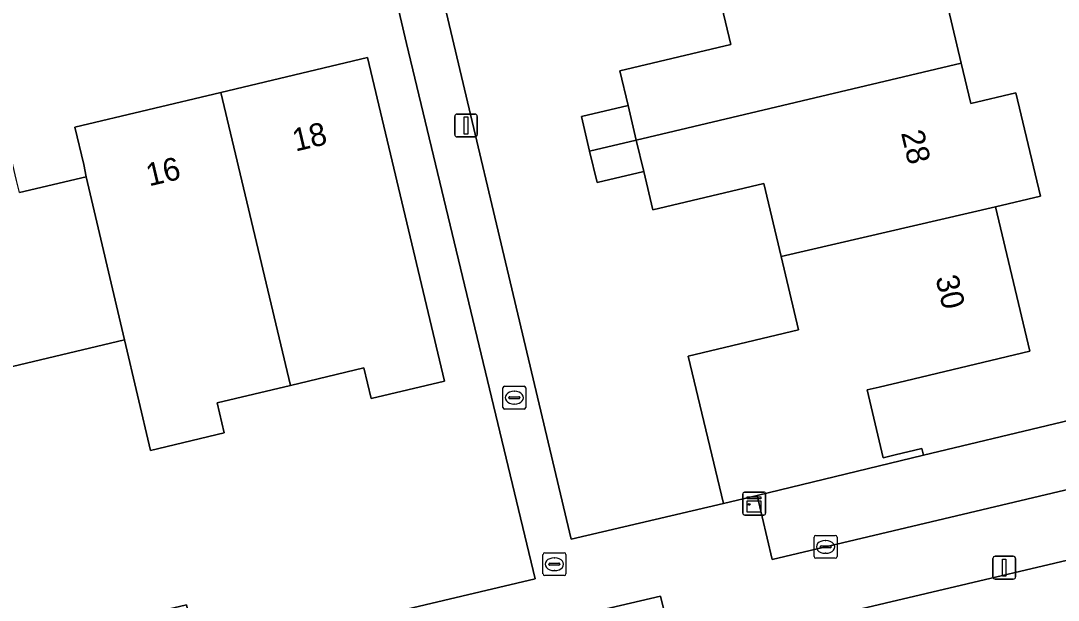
# Model space of a CAD drawing. Extents: x 157648 to 158502, y 379212 to 380938.
# Drawn here: x 158306.48 to 158351.9, y 380807.19 to 380832.57 of the extents above; entities that cross this region are included whole.
import ezdxf

# ---------------------------------------------------------------- set-up
doc = ezdxf.new("R2010")
doc.units = 0
for name, color, linetype in [('IMGEO_Erf', 7, 'Continuous'), ('IMGEO_Groenvoorziening', 7, 'Continuous'), ('IMGEO_Hek', 7, 'Continuous'), ('IMGEO_Kast', 7, 'Continuous'), ('IMGEO_Kolk', 7, 'Continuous'), ('IMGEO_Lichtmast', 7, 'Continuous'), ('IMGEO_Pand', 7, 'Continuous'), ('IMGEO_Pand_nummerreeks', 7, 'Continuous'), ('IMGEO_Rioolput', 7, 'Continuous'), ('IMGEO_Voetpad_open', 7, 'Continuous')]:
    doc.layers.add(name, color=color, linetype=linetype)

msp = doc.modelspace()

# ---------------------------------------------------------------- linework, layer by layer
at = {"layer": 'IMGEO_Erf'}
for points in [[(158346.135, 380837.142), (158347.662, 380830.717), (158348.081, 380828.951), (158350.047, 380829.418), (158351.124, 380824.885), (158349.158, 380824.417), (158350.661, 380818.095), (158345.233, 380816.805), (158344.065, 380816.528), (158343.54, 380816.403), (158344.245, 380813.436), (158344.77, 380813.561), (158345.938, 380813.838), (158346.006, 380813.552), (158363.215, 380817.667), (158352.177, 380864.073)], [(158322.972, 380841.959), (158330.575, 380809.862), (158337.257, 380811.425), (158335.708, 380817.882), (158340.536, 380819.029), (158339.773, 380822.239), (158339.011, 380825.447), (158334.155, 380824.294), (158333.757, 380825.967), (158331.714, 380825.482), (158331.389, 380826.851), (158331.028, 380828.372), (158333.071, 380828.856), (158332.71, 380830.377), (158337.566, 380831.531), (158336.781, 380834.836)], [(158278.284, 380798.647), (158313.745, 380806.99), (158314.304, 380804.661), (158329, 380808.131), (158323.379, 380831.566), (158321.058, 380841.488)], [(158306.43, 380825.041), (158309.351, 380825.735), (158309.248, 380826.274), (158308.859, 380827.913), (158315.246, 380829.43), (158321.667, 380830.956), (158325.033, 380816.793), (158321.823, 380816.03), (158321.506, 380817.366), (158318.291, 380816.602), (158315.077, 380815.839), (158315.39, 380814.522), (158312.17, 380813.757), (158311.02, 380818.596), (158304.887, 380817.139)], [(158364.564, 380811.841), (158335.11, 380804.894), (158334.498, 380807.379), (158318.481, 380803.643), (158321.807, 380789.612), (158323.266, 380789.958), (158322.059, 380795.081), (158328.42, 380796.648), (158334.809, 380798.161), (158337.107, 380788.456), (158338.879, 380788.876), (158340.617, 380789.288), (158338.891, 380796.576), (158345.168, 380798.063), (158351.466, 380799.554), (158357.767, 380801.046)]]:
    msp.add_lwpolyline(points, dxfattribs=at)
at = {"layer": 'IMGEO_Groenvoorziening'}
msp.add_lwpolyline([(158363.902, 380814.78), (158363.215, 380817.667), (158346.006, 380813.552), (158338.72, 380811.781), (158339.383, 380808.977)], close=True, dxfattribs=at)
at = {"layer": 'IMGEO_Hek'}
for points in [[(158337.257, 380811.425), (158330.575, 380809.862), (158322.972, 380841.959)], [(158323.379, 380831.566), (158329, 380808.131), (158314.304, 380804.661), (158313.745, 380806.99), (158278.284, 380798.647)]]:
    msp.add_lwpolyline(points, dxfattribs=at)
at = {"layer": 'IMGEO_Kast'}
for p, q in [((158338.169, 380811.926), (158339.01, 380811.926)), ((158339.01, 380811.926), (158338.169, 380811.926)), ((158338.094, 380811.001), (158338.094, 380811.842)), ((158338.094, 380811.842), (158338.094, 380811.001)), ((158339.094, 380811.851), (158339.094, 380811.01)), ((158339.094, 380811.01), (158339.094, 380811.851)), ((158339.019, 380810.926), (158338.178, 380810.926)), ((158338.178, 380810.926), (158339.019, 380810.926))]:
    msp.add_line(p, q, dxfattribs=at)
for points in [[(158338.289, 380811.716), (158338.889, 380811.716), (158338.889, 380811.631), (158338.289, 380811.631), (158338.289, 380811.716)], [(158338.289, 380811.541), (158338.889, 380811.541), (158338.889, 380811.052), (158338.289, 380811.052), (158338.289, 380811.541)]]:
    msp.add_lwpolyline(points, dxfattribs=at)
msp.add_circle((158338.373, 380811.39), 0.0377, dxfattribs=at)
for centre, start, end in [((158338.172, 380811.848), 92.4484, 184.2845), ((158338.172, 380811.848), 92.4484, 184.2845), ((158339.016, 380811.848), 2.4484, 94.2845), ((158339.016, 380811.848), 2.4484, 94.2845), ((158338.172, 380811.004), 182.4484, 274.2845), ((158338.172, 380811.004), 182.4484, 274.2845), ((158339.016, 380811.004), 272.4484, 4.2845), ((158339.016, 380811.004), 272.4484, 4.2845)]:
    msp.add_arc(centre, 0.0779, start, end, dxfattribs=at)
at = {"layer": 'IMGEO_Kolk'}
for p, q in [((158327.592, 380815.637), (158327.592, 380816.489)), ((158327.667, 380816.563), (158328.519, 380816.563)), ((158328.593, 380816.489), (158328.593, 380815.637)), ((158327.851, 380816.057), (158327.851, 380816.069)), ((158328.289, 380816.02), (158327.891, 380816.02)), ((158327.894, 380816.106), (158328.292, 380816.106)), ((158328.08, 380816.343), (158328.105, 380816.343)), ((158328.335, 380816.069), (158328.335, 380816.057)), ((158328.519, 380815.563), (158327.667, 380815.563)), ((158328.103, 380815.783), (158328.078, 380815.783)), ((158341.218, 380809.104), (158341.218, 380809.956)), ((158341.293, 380810.03), (158342.145, 380810.03)), ((158341.706, 380809.81), (158341.731, 380809.81)), ((158342.219, 380809.956), (158342.219, 380809.104)), ((158341.477, 380809.524), (158341.477, 380809.536)), ((158341.915, 380809.487), (158341.517, 380809.487)), ((158341.52, 380809.573), (158341.918, 380809.573)), ((158341.729, 380809.25), (158341.704, 380809.25)), ((158341.961, 380809.536), (158341.961, 380809.524)), ((158342.145, 380809.03), (158341.293, 380809.03))]:
    msp.add_line(p, q, dxfattribs=at)
for points in [[(158327.592, 380815.637), (158327.592, 380816.489)], [(158327.667, 380816.563), (158328.519, 380816.563)], [(158328.593, 380816.489), (158328.593, 380815.637)], [(158328.519, 380815.563), (158327.667, 380815.563)], [(158341.218, 380809.104), (158341.218, 380809.956)], [(158341.293, 380810.03), (158342.145, 380810.03)], [(158342.219, 380809.956), (158342.219, 380809.104)], [(158342.145, 380809.03), (158341.293, 380809.03)]]:
    msp.add_lwpolyline(points, dxfattribs=at)
for centre, radius, start, end in [((158327.669, 380816.487), 0.0765, 91.552, 178.448), ((158327.669, 380816.487), 0.0765, 91.552, 178.448), ((158328.517, 380816.487), 0.0765, 1.552, 88.448), ((158328.517, 380816.487), 0.0765, 1.552, 88.448), ((158327.891, 380816.066), 0.0403, 85.8775, 175.7526), ((158327.888, 380816.056), 0.0366, 178.938, 274.7102), ((158328.292, 380816.063), 0.043, 264.8664, 352.4533), ((158328.296, 380816.068), 0.0386, 1.7309, 96.639), ((158327.669, 380815.639), 0.0765, 181.552, 268.448), ((158327.669, 380815.639), 0.0765, 181.552, 268.448), ((158328.517, 380815.639), 0.0765, 271.552, 358.448), ((158328.517, 380815.639), 0.0765, 271.552, 358.448), ((158341.295, 380809.954), 0.0765, 91.552, 178.448), ((158341.295, 380809.954), 0.0765, 91.552, 178.448), ((158342.143, 380809.954), 0.0765, 1.552, 88.448), ((158342.143, 380809.954), 0.0765, 1.552, 88.448), ((158341.517, 380809.533), 0.0403, 85.8775, 175.7526), ((158341.514, 380809.523), 0.0366, 178.938, 274.7102), ((158341.918, 380809.53), 0.043, 264.8664, 352.4533), ((158341.922, 380809.535), 0.0386, 1.7309, 96.639), ((158341.295, 380809.106), 0.0765, 181.552, 268.448), ((158341.295, 380809.106), 0.0765, 181.552, 268.448), ((158342.143, 380809.106), 0.0765, 271.552, 358.448), ((158342.143, 380809.106), 0.0765, 271.552, 358.448)]:
    msp.add_arc(centre, radius, start, end, dxfattribs=at)
for centre, major_axis, ratio, start_param, end_param in [((158328.079, 380816.063), (-0.387, 0.002), 0.722429, 4.712389, 7.853982), ((158328.104, 380816.063), (-0.39, 0.002), 0.717154, 1.570796, 4.712389), ((158341.705, 380809.53), (-0.387, 0.002), 0.722429, 4.712389, 7.853982), ((158341.73, 380809.53), (-0.39, 0.002), 0.717154, 1.570796, 4.712389)]:
    msp.add_ellipse(centre, major_axis=major_axis, ratio=ratio, start_param=start_param, end_param=end_param, dxfattribs=at)
at = {"layer": 'IMGEO_Lichtmast'}
for p, q in [((158325.482, 380827.58), (158325.482, 380828.38)), ((158325.482, 380828.38), (158325.482, 380827.58)), ((158325.582, 380828.48), (158326.372, 380828.48)), ((158326.372, 380828.48), (158325.582, 380828.48)), ((158326.472, 380828.38), (158326.472, 380827.58)), ((158326.472, 380827.58), (158326.472, 380828.38)), ((158326.372, 380827.48), (158325.582, 380827.48)), ((158325.582, 380827.48), (158326.372, 380827.48)), ((158349.047, 380808.217), (158349.047, 380809.017)), ((158349.047, 380809.017), (158349.047, 380808.217)), ((158349.147, 380809.117), (158349.937, 380809.117)), ((158349.937, 380809.117), (158349.147, 380809.117)), ((158350.037, 380809.017), (158350.037, 380808.217)), ((158350.037, 380808.217), (158350.037, 380809.017)), ((158349.937, 380808.117), (158349.147, 380808.117)), ((158349.147, 380808.117), (158349.937, 380808.117))]:
    msp.add_line(p, q, dxfattribs=at)
for points in [[(158325.902, 380828.355), (158326.052, 380828.355), (158326.052, 380827.605), (158325.902, 380827.605), (158325.902, 380828.355)], [(158349.467, 380808.992), (158349.617, 380808.992), (158349.617, 380808.242), (158349.467, 380808.242), (158349.467, 380808.992)]]:
    msp.add_lwpolyline(points, dxfattribs=at)
for centre, start, end in [((158325.582, 380828.38), 90, 180), ((158325.582, 380828.38), 90, 180), ((158326.372, 380828.38), 0, 90), ((158326.372, 380828.38), 360, 90), ((158325.582, 380827.58), 180, 270), ((158325.582, 380827.58), 180, 270), ((158326.372, 380827.58), 270, 0), ((158326.372, 380827.58), 270, 0), ((158349.147, 380809.017), 90, 180), ((158349.147, 380809.017), 90, 180), ((158349.937, 380809.017), 0, 90), ((158349.937, 380809.017), 360, 90), ((158349.147, 380808.217), 180, 270), ((158349.147, 380808.217), 180, 270), ((158349.937, 380808.217), 270, 0), ((158349.937, 380808.217), 270, 0)]:
    msp.add_arc(centre, 0.1, start, end, dxfattribs=at)
at = {"layer": 'IMGEO_Pand'}
for points in [[(158346.135, 380837.142), (158344.492, 380836.752), (158343.976, 380836.629), (158336.781, 380834.836), (158337.566, 380831.531), (158332.71, 380830.377), (158333.071, 380828.856), (158333.432, 380827.336), (158347.662, 380830.717)], [(158311.02, 380818.596), (158309.351, 380825.735), (158306.43, 380825.041), (158306.303, 380825.574), (158304.745, 380832.131), (158298.275, 380830.594), (158300.475, 380821.332), (158303.708, 380822.1), (158304.887, 380817.139)], [(158318.291, 380816.602), (158321.506, 380817.366), (158321.823, 380816.03), (158325.033, 380816.793), (158321.667, 380830.956), (158315.246, 380829.43)], [(158350.047, 380829.418), (158348.081, 380828.951), (158347.662, 380830.717), (158333.432, 380827.336), (158333.757, 380825.967), (158334.155, 380824.294), (158339.011, 380825.447), (158339.773, 380822.239), (158349.158, 380824.417), (158351.124, 380824.885)], [(158311.02, 380818.596), (158312.17, 380813.757), (158315.39, 380814.522), (158315.077, 380815.839), (158318.291, 380816.602), (158315.246, 380829.43), (158308.859, 380827.913), (158309.248, 380826.274), (158309.351, 380825.735)], [(158333.071, 380828.856), (158331.028, 380828.372), (158331.389, 380826.851), (158333.432, 380827.336)], [(158333.432, 380827.336), (158331.389, 380826.851), (158331.714, 380825.482), (158333.757, 380825.967)], [(158350.661, 380818.095), (158349.158, 380824.417), (158339.773, 380822.239), (158340.536, 380819.029), (158335.708, 380817.882), (158337.257, 380811.425), (158338.72, 380811.781), (158346.006, 380813.552), (158345.938, 380813.838), (158344.77, 380813.561), (158344.245, 380813.436), (158343.54, 380816.403), (158344.065, 380816.528), (158345.233, 380816.805)]]:
    msp.add_lwpolyline(points, close=True, dxfattribs=at)
at = {"layer": 'IMGEO_Rioolput'}
for p, q in [((158329.348, 380808.345), (158329.348, 380809.197)), ((158329.423, 380809.271), (158330.275, 380809.271)), ((158330.349, 380809.197), (158330.349, 380808.345)), ((158329.607, 380808.765), (158329.607, 380808.777)), ((158330.045, 380808.728), (158329.647, 380808.728)), ((158329.65, 380808.814), (158330.048, 380808.814)), ((158329.836, 380809.051), (158329.861, 380809.051)), ((158330.091, 380808.777), (158330.091, 380808.765)), ((158330.275, 380808.271), (158329.423, 380808.271)), ((158329.859, 380808.491), (158329.834, 380808.491))]:
    msp.add_line(p, q, dxfattribs=at)
for points in [[(158329.348, 380808.345), (158329.348, 380809.197)], [(158329.423, 380809.271), (158330.275, 380809.271)], [(158330.349, 380809.197), (158330.349, 380808.345)], [(158330.275, 380808.271), (158329.423, 380808.271)]]:
    msp.add_lwpolyline(points, dxfattribs=at)
for centre, radius, start, end in [((158329.425, 380809.195), 0.0765, 91.552, 178.448), ((158329.425, 380809.195), 0.0765, 91.552, 178.448), ((158330.273, 380809.195), 0.0765, 1.552, 88.448), ((158330.273, 380809.195), 0.0765, 1.552, 88.448), ((158329.647, 380808.774), 0.0403, 85.8775, 175.7526), ((158329.644, 380808.764), 0.0366, 178.938, 274.7102), ((158330.048, 380808.771), 0.043, 264.8664, 352.4533), ((158330.052, 380808.776), 0.0386, 1.7309, 96.639), ((158329.425, 380808.347), 0.0765, 181.552, 268.448), ((158329.425, 380808.347), 0.0765, 181.552, 268.448), ((158330.273, 380808.347), 0.0765, 271.552, 358.448), ((158330.273, 380808.347), 0.0765, 271.552, 358.448)]:
    msp.add_arc(centre, radius, start, end, dxfattribs=at)
for centre, major_axis, ratio, start_param, end_param in [((158329.835, 380808.771), (-0.387, 0.002), 0.722429, 4.712389, 7.853982), ((158329.86, 380808.771), (-0.39, 0.002), 0.717154, 1.570796, 4.712389)]:
    msp.add_ellipse(centre, major_axis=major_axis, ratio=ratio, start_param=start_param, end_param=end_param, dxfattribs=at)
at = {"layer": 'IMGEO_Voetpad_open'}
msp.add_lwpolyline([(158322.972, 380841.959), (158321.058, 380841.488), (158323.379, 380831.566), (158329, 380808.131), (158314.304, 380804.661), (158313.745, 380806.99), (158278.284, 380798.647), (158278.739, 380796.726), (158289.939, 380799.382), (158298.77, 380801.471), (158306.285, 380803.232), (158306.826, 380800.924), (158308.853, 380801.397), (158318.481, 380803.643), (158334.498, 380807.379), (158335.11, 380804.894), (158364.564, 380811.841), (158363.902, 380814.78), (158339.383, 380808.977), (158338.72, 380811.781), (158337.257, 380811.425), (158330.575, 380809.862)], close=True, dxfattribs=at)

# ---------------------------------------------------------------- texts
at = {"layer": 'IMGEO_Pand_nummerreeks'}
for s, rotation, p in [('18', 13.3649, (158318.511, 380826.835)), ('28', 283.3669, (158345.017, 380827.661)), ('16', 13.3649, (158312.104, 380825.312)), ('30', 283.3669, (158346.525, 380821.312))]:
    msp.add_text(s, height=1, rotation=rotation, dxfattribs=at).set_placement(p)

doc.saveas('drawing.dxf')
